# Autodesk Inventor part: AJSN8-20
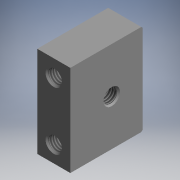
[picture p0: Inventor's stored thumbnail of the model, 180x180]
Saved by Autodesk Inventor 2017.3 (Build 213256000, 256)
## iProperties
Part Number: AJSN8-20
Material: Generic
Catalog Web Link: www.cadenas.de
Description: AJSN, AJSNM, AJSNS, AJSS, AJSSM, AJSSS-Locating Screw Stopper Blocks - With Counterbore and Tap Holes Type - H Dimension Selection
Vendor: MISUMI
Document SubType Name: Modeling
Designer: partserver
Manufacturer: MISUMI
Mass: 20.8809 g
Surface Area: 73.2299 cm^2
Volume: 20.8809 cm^3
Density: 1 g/cm^3
Appearance: PSOLRGB-175-175-175
Category: PARTsolutions
Company: MISUMI
Title: AJSN8-20
Author: Cadenas PARTsolutions
Comments: Locating Screw Stopper Blocks - With Counterbore and Tap Holes Type - H Dimension Selection
PSOL_IDENT_0: {$CADENAS_DATA\23d-libs\misumi\metric\15_locating_components\ajss.prj},203 {VTYP=3D},{NB=AJSN8-20},{
PSOL_IDENT_1: LINA=AJSN8-20},{NN=AJSN, AJSNM, AJSNS, AJSS, AJSSM, AJSSS},{DATE=02.06.2021 05:57:37},{GEOMDATE=26.1
PSOL_IDENT_2: 0.2015 02:07:54},{VERSION=},{LINEID=50},{WBVAR=TRS,MAT,ST,HS},{WBNUMERIC=HS}  {NB=AJSN8-20},{LINA=AJ
PSOL_IDENT_3: SN8-20},{KT=DUMMY},{PN=AJSN8-20},{TYS=1},{TRS=CT},{TS=ST},{TYPE=AJSN},{MAT=1},{ST=BO},{ST1='BO', 'Bl
PSOL_IDENT_4: ack Oxide', 'ENP', 'Electroless Nickel Plating'},{M=8},{HS=20},{H2=15,20,25,30},{H3=[15:35/1]},{H1=1
PSOL_IDENT_5: 5},{T=16},{MP=8x1.25},{MC=8x1.25},{MCM=1.25},{MF=8x0.75},{MFM=0.75},{MMIN=1.25},{L=44},{L1=44},{L2=5
PSOL_IDENT_6: 0},{P1=28},{P2=10},{DD1=11},{DD2=6.5},{DD3=4},{LL1=6.5},{LL2=6.0},{E=5},{N=M8},{NM=8},{HSA=15,20,25,
PSOL_IDENT_7: 30},{TSA='ST','Standard','NT','T Dimension Negative Tolerance','DH','with Dowel Holes'},{X=1},{PITCH=
PSOL_IDENT_8: 1.25}
NB: AJSN8-20
NN: AJSN, AJSNM, AJSNS, AJSS, AJSSM, AJSSS
NT: Locating Screw Stopper Blocks - With Counterbore and Tap Holes Type - H Dimension Selection
NBSYN: $PN.
LINA: AJSN8-20
CATALOG: Misumi
PN: AJSN8-20
TRS: Coarse Thread
MAT: Low Carbon Steel
ST: Black Oxide
M: 8
HS: 20
H1: 15
T: 16
MP: 8x1.25
L: 44
P1: 28
DD1: 11
DD2: 6.5
LL1: 6.5
N: M8
SUPPLIER: MISUMI
ARTICLENO: AJSN8-20
BOMINFO: AJSN8-20
CREATOR: CADENAS GmbH
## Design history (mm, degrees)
sketch "Sketch_1"
  geometry: L1 (34.293, 22)-(0, 22); L2 (0, 22)-(0, -22); L3 (0, -22)-(34.293, -22); L4 (34.293, -22)-(35, -21.293); L5 (35, -21.293)-(35, 21.293); L6 (35, 21.293)-(34.293, 22)
  constraints: 12 end point
extrude "Extrusion1" join sketch "Sketch_1" stored distance "d0" = 16; taper "d1" = 0 deg
sketch "Sketch2"
  geometry: 1 further point
hole "Hole1" sketch "Sketch2" at (8, 35.293) diameter "d2" = 6.5; stored, may be unused: countersink angle "d6" = 90 deg, drill point angle "d8" = 0 deg; dims "d3" = 6, "d4" = 11, "d5" = 6.5, "d7" = 19
sketch "Sketch_10"
  geometry: L1 (0, -14)-(16, -14); L2 (16, -14)-(16, -17.323); L3 (16, -17.323)-(0.676, -17.323); L4 (0.676, -17.323)-(0, -18); L5 (0, -18)-(0, -14); L6 (0, -14)-(16, -14)
  constraints: 12 end point
revolve "Revolution1" sketch "Sketch_10" stored, may be unused: angle "d9" = 360 deg
thread "Thread1" dims "d10" = 15.3235, "d11" = 0
sketch "Sketch_3"
  geometry: L1 (8, 20)-(-8, 20); L2 (-8, 20)-(-8, 24); L3 (-8, 24)-(-7.324, 23.323); L4 (-7.324, 23.323)-(7.324, 23.323); L5 (7.324, 23.323)-(8, 24); L6 (8, 24)-(8, 20); L7 (8, 20)-(-8, 20)
  constraints: 14 end point
revolve "Revolution2" sketch "Sketch_3" stored, may be unused: angle "d12" = 360 deg
thread "Thread2" dims "d13" = 14.647, "d14" = 0
sketch "Sketch6"
  geometry: 1 further point
hole "Hole2" sketch "Sketch6" at (8, 7.293) diameter "d15" = 6.5; stored, may be unused: countersink angle "d19" = 90 deg, drill point angle "d21" = 0 deg; dims "d16" = 6, "d17" = 11, "d18" = 6.5, "d20" = 19
sketch "Sketch_15"
  geometry: L1 (0, 14)-(16, 14); L2 (16, 14)-(16, 10.677); L3 (16, 10.677)-(0.676, 10.677); L4 (0.676, 10.677)-(0, 10); L5 (0, 10)-(0, 14); L6 (0, 14)-(16, 14)
  constraints: 12 end point
revolve "Revolution3" sketch "Sketch_15" stored, may be unused: angle "d22" = 360 deg
thread "Thread3" dims "d23" = 15.3235, "d24" = 0
node "blosk_to_screw_XY"
node "blosk_to_screw_YZ"
node "blosk_to_screw_ZX"
node "blosk_to_screw_X"
node "blosk_to_screw_Y"
node "blosk_to_screw_Z"
node "blosk_to_screw_Center"
node "bolt1_cb_1_XY"
node "bolt1_cb_1_YZ"
node "bolt1_cb_1_ZX"
node "bolt1_cb_1_X"
node "bolt1_cb_1_Y"
node "bolt1_cb_1_Z"
node "bolt1_cb_1_Center"
node "bolt1_cb_2_XY"
node "bolt1_cb_2_YZ"
node "bolt1_cb_2_ZX"
node "bolt1_cb_2_X"
node "bolt1_cb_2_Y"
node "bolt1_cb_2_Z"
node "bolt1_cb_2_Center"
node "to_dummy_cb_XY"
node "to_dummy_cb_YZ"
node "to_dummy_cb_ZX"
node "to_dummy_cb_X"
node "to_dummy_cb_Y"
node "to_dummy_cb_Z"
node "to_dummy_cb_Center"
body "Solid1"
other parameters: "d25" = 0, "d26" = 0, "d27" = 0
